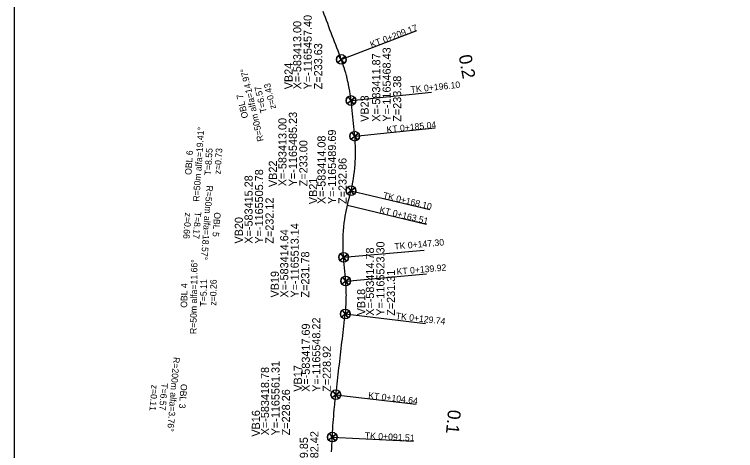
# Model space of a CAD drawing. Extents: x -583517 to -548566, y -1166112 to -1101582.
# Drawn here: x -583517 to -583294.2, y -1165565.5 to -1165430.8 of the extents above; entities that cross this region are included whole.
import ezdxf

# ---------------------------------------------------------------- set-up
doc = ezdxf.new("R2010")
doc.units = 0
for name, color, linetype in [('13', 7, 'Continuous'), ('59', 7, 'Continuous'), ('8', 7, 'Continuous'), ('Body pricny rez', 7, 'Continuous'), ('Popis pricneho profilu', 7, 'Continuous')]:
    doc.layers.add(name, color=color, linetype=linetype)

msp = doc.modelspace()

# ---------------------------------------------------------------- linework, layer by layer
at = {"layer": '13'}
for points in [[(-583416, -1165444.72), (-583392.64, -1165435.83)], [(-583413, -1165457.4), (-583388.13, -1165454.85)], [(-583411.87, -1165468.4), (-583387, -1165465.85)], [(-583413, -1165485.23), (-583388.7, -1165491.09)], [(-583414.08, -1165489.69), (-583389.77, -1165495.55)], [(-583415.28, -1165505.78), (-583390.38, -1165503.6)], [(-583414.64, -1165513.14), (-583389.73, -1165510.95)], [(-583414.78, -1165523.3), (-583389.95, -1165526.19)], [(-583417.69, -1165548.22), (-583392.86, -1165551.12)], [(-583418.78, -1165561.31), (-583393.81, -1165562.57)]]:
    msp.add_lwpolyline(points, dxfattribs=at)
at = {"layer": '8'}
for p, q in [((-583415.11, -1165445.93), (-583416.9, -1165443.52)), ((-583416, -1165444.72), (-583416.9, -1165443.52)), ((-583417.21, -1165445.62), (-583414.8, -1165443.83)), ((-583417.21, -1165445.62), (-583416, -1165444.72)), ((-583414.8, -1165443.83), (-583416, -1165444.72)), ((-583414.8, -1165443.83), (-583416, -1165444.72)), ((-583416, -1165444.72), (-583415.11, -1165445.93)), ((-583416, -1165444.72), (-583415.11, -1165445.93)), ((-583414.2, -1165458.3), (-583411.79, -1165456.51)), ((-583412.1, -1165458.61), (-583413.89, -1165456.2)), ((-583413, -1165457.4), (-583413.89, -1165456.2)), ((-583411.79, -1165456.51), (-583413, -1165457.4)), ((-583411.79, -1165456.51), (-583413, -1165457.4)), ((-583414.2, -1165458.3), (-583413, -1165457.4)), ((-583413, -1165457.4), (-583412.1, -1165458.61)), ((-583413, -1165457.4), (-583412.1, -1165458.61)), ((-583413.07, -1165469.3), (-583410.67, -1165467.51)), ((-583410.97, -1165469.61), (-583412.76, -1165467.2)), ((-583411.87, -1165468.4), (-583412.76, -1165467.2)), ((-583410.66, -1165467.51), (-583411.87, -1165468.4)), ((-583410.66, -1165467.51), (-583411.87, -1165468.4)), ((-583413.07, -1165469.3), (-583411.87, -1165468.4)), ((-583411.87, -1165468.4), (-583410.97, -1165469.61)), ((-583411.87, -1165468.4), (-583410.97, -1165469.61)), ((-583414.21, -1165486.12), (-583413, -1165485.23)), ((-583414.2, -1165486.12), (-583411.8, -1165484.33)), ((-583412.11, -1165486.43), (-583413.9, -1165484.02)), ((-583413, -1165485.23), (-583413.9, -1165484.02)), ((-583411.8, -1165484.33), (-583413, -1165485.23)), ((-583411.8, -1165484.33), (-583413, -1165485.23)), ((-583413, -1165485.23), (-583412.11, -1165486.43)), ((-583413, -1165485.23), (-583412.11, -1165486.43)), ((-583416.48, -1165506.68), (-583414.08, -1165504.89)), ((-583416.48, -1165506.68), (-583415.28, -1165505.78)), ((-583415.28, -1165505.78), (-583416.18, -1165504.58)), ((-583414.39, -1165506.98), (-583416.17, -1165504.58)), ((-583414.08, -1165504.89), (-583415.28, -1165505.78)), ((-583414.08, -1165504.89), (-583415.28, -1165505.78)), ((-583415.28, -1165505.78), (-583414.38, -1165506.98)), ((-583415.28, -1165505.78), (-583414.38, -1165506.98)), ((-583415.84, -1165514.03), (-583413.43, -1165512.24)), ((-583413.74, -1165514.34), (-583415.53, -1165511.93)), ((-583414.64, -1165513.14), (-583415.53, -1165511.93)), ((-583413.43, -1165512.24), (-583414.64, -1165513.14)), ((-583413.43, -1165512.24), (-583414.64, -1165513.14)), ((-583415.84, -1165514.03), (-583414.64, -1165513.14)), ((-583414.64, -1165513.14), (-583413.74, -1165514.34)), ((-583414.64, -1165513.14), (-583413.74, -1165514.34)), ((-583415.99, -1165524.19), (-583414.78, -1165523.3)), ((-583415.98, -1165524.19), (-583413.58, -1165522.4)), ((-583413.89, -1165524.5), (-583415.68, -1165522.09)), ((-583414.78, -1165523.3), (-583415.68, -1165522.09)), ((-583413.58, -1165522.4), (-583414.78, -1165523.3)), ((-583413.58, -1165522.4), (-583414.78, -1165523.3)), ((-583414.78, -1165523.3), (-583413.89, -1165524.5)), ((-583414.78, -1165523.3), (-583413.89, -1165524.5)), ((-583418.89, -1165549.12), (-583416.48, -1165547.33)), ((-583418.89, -1165549.12), (-583417.69, -1165548.22)), ((-583416.79, -1165549.43), (-583418.58, -1165547.02)), ((-583417.69, -1165548.22), (-583418.58, -1165547.02)), ((-583416.48, -1165547.33), (-583417.69, -1165548.22)), ((-583416.48, -1165547.33), (-583417.69, -1165548.22)), ((-583417.69, -1165548.22), (-583416.79, -1165549.43)), ((-583417.69, -1165548.22), (-583416.79, -1165549.43)), ((-583419.99, -1165562.2), (-583418.78, -1165561.31)), ((-583419.98, -1165562.2), (-583417.58, -1165560.41)), ((-583418.78, -1165561.31), (-583419.68, -1165560.1)), ((-583417.89, -1165562.51), (-583419.68, -1165560.11)), ((-583417.58, -1165560.41), (-583418.78, -1165561.31)), ((-583417.58, -1165560.41), (-583418.78, -1165561.31)), ((-583418.78, -1165561.31), (-583417.89, -1165562.51)), ((-583418.78, -1165561.31), (-583417.89, -1165562.51))]:
    msp.add_line(p, q, dxfattribs=at)
for centre in [(-583416, -1165444.72), (-583413, -1165457.4), (-583411.87, -1165468.4), (-583413, -1165485.23), (-583415.28, -1165505.78), (-583414.64, -1165513.14), (-583414.78, -1165523.3), (-583417.69, -1165548.22), (-583418.78, -1165561.31)]:
    msp.add_circle(centre, 1.5, dxfattribs=at)
for centre, start, end in [((-583416, -1165444.72), 126.6271, 216.6271), ((-583416, -1165444.72), 306.6271, 36.6271), ((-583416, -1165444.72), 306.6271, 36.6271), ((-583413, -1165457.4), 126.6271, 216.6271), ((-583413, -1165457.4), 306.6271, 36.6271), ((-583413, -1165457.4), 306.6271, 36.6271), ((-583411.87, -1165468.4), 126.6271, 216.6271), ((-583411.87, -1165468.4), 306.6271, 36.6271), ((-583411.87, -1165468.4), 306.6271, 36.6271), ((-583413, -1165485.23), 126.6271, 216.6271), ((-583413, -1165485.23), 306.6271, 36.6271), ((-583413, -1165485.23), 306.6271, 36.6271), ((-583415.28, -1165505.78), 126.6271, 216.6271), ((-583415.28, -1165505.78), 306.6271, 36.6271), ((-583415.28, -1165505.78), 306.6271, 36.6271), ((-583414.64, -1165513.14), 126.6271, 216.6271), ((-583414.64, -1165513.14), 306.6271, 36.6271), ((-583414.64, -1165513.14), 306.6271, 36.6271), ((-583414.78, -1165523.3), 126.6271, 216.6271), ((-583414.78, -1165523.3), 306.6271, 36.6271), ((-583414.78, -1165523.3), 306.6271, 36.6271), ((-583417.69, -1165548.22), 126.6271, 216.6271), ((-583417.69, -1165548.22), 306.6271, 36.6271), ((-583417.69, -1165548.22), 306.6271, 36.6271), ((-583418.78, -1165561.31), 126.6271, 216.6271), ((-583418.78, -1165561.31), 306.6271, 36.6271), ((-583418.78, -1165561.31), 306.6271, 36.6271)]:
    msp.add_arc(centre, 1.5, start, end, dxfattribs=at)
at = {"layer": 'Body pricny rez'}
msp.add_lwpolyline([(-583419.01, -1165565.81), (-583418.96, -1165564.81), (-583418.91, -1165563.82), (-583418.86, -1165562.82), (-583418.81, -1165561.82), (-583418.78, -1165561.31), (-583418.76, -1165560.82), (-583418.7, -1165559.82), (-583418.64, -1165558.82), (-583418.59, -1165558.03), (-583418.57, -1165557.83), (-583418.5, -1165556.83), (-583418.43, -1165555.83), (-583418.35, -1165554.83), (-583418.34, -1165554.76), (-583418.26, -1165553.84), (-583418.17, -1165552.84), (-583418.08, -1165551.85), (-583418.04, -1165551.49), (-583417.98, -1165550.85), (-583417.87, -1165549.86), (-583417.76, -1165548.86), (-583417.69, -1165548.22), (-583417.65, -1165547.87), (-583417.53, -1165546.88), (-583417.42, -1165545.88), (-583417.3, -1165544.89), (-583417.18, -1165543.9), (-583417.07, -1165542.9), (-583416.95, -1165541.91), (-583416.84, -1165540.92), (-583416.72, -1165539.92), (-583416.6, -1165538.93), (-583416.49, -1165537.94), (-583416.37, -1165536.94), (-583416.26, -1165535.95), (-583416.14, -1165534.96), (-583416.03, -1165533.96), (-583415.91, -1165532.97), (-583415.79, -1165531.98), (-583415.68, -1165530.98), (-583415.56, -1165529.99), (-583415.45, -1165529), (-583415.33, -1165528), (-583415.21, -1165527.01), (-583415.1, -1165526.02), (-583414.98, -1165525.02), (-583414.87, -1165524.03), (-583414.78, -1165523.3), (-583414.75, -1165523.04), (-583414.65, -1165522.04), (-583414.63, -1165521.85), (-583414.57, -1165521.05), (-583414.53, -1165520.4), (-583414.51, -1165520.05), (-583414.47, -1165519.05), (-583414.46, -1165518.95), (-583414.45, -1165518.05), (-583414.44, -1165517.49), (-583414.45, -1165517.05), (-583414.47, -1165516.05), (-583414.47, -1165516.04), (-583414.5, -1165515.05), (-583414.53, -1165514.59), (-583414.56, -1165514.05), (-583414.64, -1165513.14), (-583414.64, -1165513.06), (-583414.73, -1165512.06), (-583414.82, -1165511.06), (-583414.9, -1165510.07), (-583414.99, -1165509.07), (-583415.08, -1165508.07), (-583415.17, -1165507.08), (-583415.25, -1165506.08), (-583415.28, -1165505.78), (-583415.34, -1165505.09), (-583415.39, -1165504.31), (-583415.4, -1165504.09), (-583415.44, -1165503.09), (-583415.45, -1165502.84), (-583415.47, -1165502.09), (-583415.47, -1165501.37), (-583415.47, -1165501.09), (-583415.45, -1165500.09), (-583415.45, -1165499.89), (-583415.42, -1165499.09), (-583415.38, -1165498.42), (-583415.36, -1165498.09), (-583415.28, -1165497.09), (-583415.27, -1165496.95), (-583415.19, -1165496.1), (-583415.12, -1165495.49), (-583415.07, -1165495.11), (-583414.94, -1165494.11), (-583414.92, -1165494.03), (-583414.78, -1165493.13), (-583414.68, -1165492.58), (-583414.6, -1165492.14), (-583414.41, -1165491.16), (-583414.4, -1165491.13), (-583414.19, -1165490.19), (-583414.08, -1165489.69), (-583413.96, -1165489.21), (-583413.73, -1165488.24), (-583413.49, -1165487.27), (-583413.26, -1165486.3), (-583413.02, -1165485.32), (-583413, -1165485.23), (-583412.8, -1165484.35), (-583412.66, -1165483.72), (-583412.59, -1165483.37), (-583412.4, -1165482.39), (-583412.37, -1165482.21), (-583412.24, -1165481.4), (-583412.13, -1165480.69), (-583412.09, -1165480.41), (-583411.96, -1165479.42), (-583411.93, -1165479.16), (-583411.85, -1165478.43), (-583411.78, -1165477.63), (-583411.76, -1165477.43), (-583411.69, -1165476.44), (-583411.68, -1165476.09), (-583411.65, -1165475.44), (-583411.62, -1165474.56), (-583411.62, -1165474.44), (-583411.61, -1165473.44), (-583411.61, -1165473.02), (-583411.62, -1165472.44), (-583411.65, -1165471.48), (-583411.65, -1165471.44), (-583411.7, -1165470.44), (-583411.74, -1165469.94), (-583411.77, -1165469.44), (-583411.86, -1165468.45), (-583411.87, -1165468.4), (-583411.97, -1165467.45), (-583412.07, -1165466.46), (-583412.17, -1165465.46), (-583412.27, -1165464.47), (-583412.38, -1165463.47), (-583412.48, -1165462.48), (-583412.58, -1165461.48), (-583412.68, -1165460.49), (-583412.78, -1165459.49), (-583412.89, -1165458.5), (-583412.99, -1165457.5), (-583413, -1165457.4), (-583413.1, -1165456.51), (-583413.17, -1165455.96), (-583413.23, -1165455.52), (-583413.38, -1165454.53), (-583413.38, -1165454.52), (-583413.55, -1165453.54), (-583413.63, -1165453.09), (-583413.74, -1165452.56), (-583413.92, -1165451.67), (-583413.94, -1165451.58), (-583414.17, -1165450.61), (-583414.26, -1165450.26), (-583414.33, -1165449.98), (-583414.42, -1165449.64), (-583414.64, -1165448.86), (-583414.69, -1165448.68), (-583414.97, -1165447.72), (-583415.05, -1165447.47), (-583415.28, -1165446.77), (-583415.51, -1165446.09), (-583415.6, -1165445.82), (-583415.94, -1165444.88), (-583416, -1165444.72), (-583416.3, -1165443.95), (-583416.66, -1165443.01), (-583417.01, -1165442.08), (-583417.37, -1165441.14), (-583417.72, -1165440.21), (-583418.08, -1165439.27), (-583418.43, -1165438.34), (-583418.79, -1165437.4), (-583419.15, -1165436.47), (-583419.5, -1165435.53), (-583419.86, -1165434.6), (-583420.21, -1165433.67), (-583420.57, -1165432.73), (-583420.92, -1165431.8), (-583421.28, -1165430.86), (-583421.63, -1165429.93)], dxfattribs=at)
at = {"layer": 'Popis pricneho profilu'}
msp.add_lwpolyline([(-583516.97, -1166111.82), (-583516.97, -1165166.82), (-583071.47, -1165166.82), (-583071.47, -1166111.82)], close=True, dxfattribs=at)

# ---------------------------------------------------------------- texts
at = {"layer": '13'}
for s, height, rotation, p in [('KT 0+209.17', 2, 20.8304, (-583406.66, -1165441.17)), ('0.2', 4, 280.323, (-583379.78, -1165443.6)), ('R=50m alfa=14.97%%d', 2, 103.3431, (-583439.95, -1165469.8)), ('   z=0.43', 2, 103.3431, (-583435.64, -1165461.97)), ('TK 0+196.10', 2, 5.8558, (-583394.51, -1165455.02)), ('  T=6.57', 2, 103.3431, (-583438.62, -1165462.43)), ('OBL 7', 2, 103.3431, (-583444.73, -1165462.64)), ('R=50m alfa=19.41%%d', 2, 86.1499, (-583459.86, -1165488.67)), ('KT 0+185.04', 2, 5.8558, (-583401.92, -1165467.38)), ('  T=8.55', 2, 86.1499, (-583456.4, -1165482.03)), ('   z=0.73', 2, 86.1499, (-583453.43, -1165482.46)), ('OBL 6', 2, 86.1499, (-583462.31, -1165480.42)), ('R=50m alfa=18.57%%d', 2, 265.7276, (-583457.62, -1165483.57)), ('TK 0+168.10', 2, 346.4441, (-583403.28, -1165487.57)), ('KT 0+163.51', 2, 346.4441, (-583404.36, -1165492.04)), ('   z=0.66', 2, 265.7276, (-583464.09, -1165489.73)), ('  T=8.17', 2, 265.7276, (-583461.12, -1165490.19)), ('OBL 5', 2, 265.7276, (-583455.23, -1165491.83)), ('TK 0+147.30', 2, 5.0111, (-583399.52, -1165503.45)), ('R=50m alfa=11.66%%d', 2, 89.1791, (-583460.74, -1165529.51)), ('KT 0+139.92', 2, 5.0111, (-583398.83, -1165511.22)), ('OBL 4', 2, 89.1791, (-583463.62, -1165521.4)), ('  T=5.11', 2, 89.1791, (-583457.64, -1165522.5)), ('   z=0.26', 2, 89.1791, (-583454.65, -1165522.97)), ('TK 0+129.74', 2, 353.347, (-583399.26, -1165524.82)), ('R=200m alfa=3.76%%d', 2, 265.228, (-583467.87, -1165536.54)), ('   z=0.11', 2, 265.228, (-583474.42, -1165542.84)), ('  T=6.57', 2, 265.228, (-583471.43, -1165543.13)), ('OBL 3', 2, 265.228, (-583465.55, -1165544.83)), ('KT 0+104.64', 2, 353.347, (-583407.76, -1165549.38)), ('0.1', 4, 264.677, (-583383.01, -1165552.73)), ('TK 0+091.51', 2, 357.1091, (-583408.79, -1165561.81))]:
    msp.add_text(s, height=height, rotation=rotation, dxfattribs=at).set_placement(p)
at = {"layer": '59'}
for s, p in [('Y=-1165457.40', (-583425.14, -1165453.93)), ('X=-583413.00', (-583428.37, -1165453.93)), ('Z=233.63', (-583421.9, -1165453.93)), ('Y=-1165468.43', (-583400.75, -1165463.95)), ('X=-583411.87', (-583403.98, -1165463.95)), ('VB24', (-583431.05, -1165453.93)), ('Z=233.38', (-583397.51, -1165463.95)), ('VB23', (-583407.55, -1165463.99)), ('Y=-1165485.23', (-583429.71, -1165483.87)), ('X=-583413.00', (-583432.94, -1165483.87)), ('Y=-1165489.69', (-583417.63, -1165489.33)), ('Z=233.00', (-583426.47, -1165483.87)), ('X=-583414.08', (-583420.86, -1165489.33)), ('VB22', (-583435.9, -1165484.11)), ('Z=232.86', (-583414.39, -1165489.33)), ('Y=-1165505.78', (-583440.16, -1165501.58)), ('X=-583415.28', (-583443.4, -1165501.58)), ('VB21', (-583423.47, -1165489.4)), ('Z=232.12', (-583436.93, -1165501.58)), ('VB20', (-583446.41, -1165501.55)), ('Y=-1165513.14', (-583429.15, -1165518.23)), ('X=-583414.64', (-583432.38, -1165518.23)), ('Y=-1165523.30', (-583402.67, -1165523.87)), ('X=-583414.78', (-583405.9, -1165523.87)), ('Z=231.78', (-583425.91, -1165518.23)), ('VB19', (-583435.3, -1165518.21)), ('Z=231.31', (-583399.43, -1165523.87)), ('VB18', (-583408.62, -1165523.72)), ('Y=-1165548.22', (-583422.49, -1165547.34)), ('X=-583417.69', (-583425.73, -1165547.34)), ('Z=228.92', (-583419.25, -1165547.34)), ('Y=-1165561.31', (-583435.09, -1165560.76)), ('VB17', (-583428.19, -1165547.28)), ('X=-583418.78', (-583438.33, -1165560.76)), ('Z=228.26', (-583431.86, -1165560.76)), ('VB16', (-583441.14, -1165561.17)), ('X=-583419.85', (-583426.32, -1165582.42)), ('Y=-1165582.42', (-583423.08, -1165582.42))]:
    msp.add_text(s, height=2.5, rotation=90, dxfattribs=at).set_placement(p)

doc.saveas('drawing.dxf')
